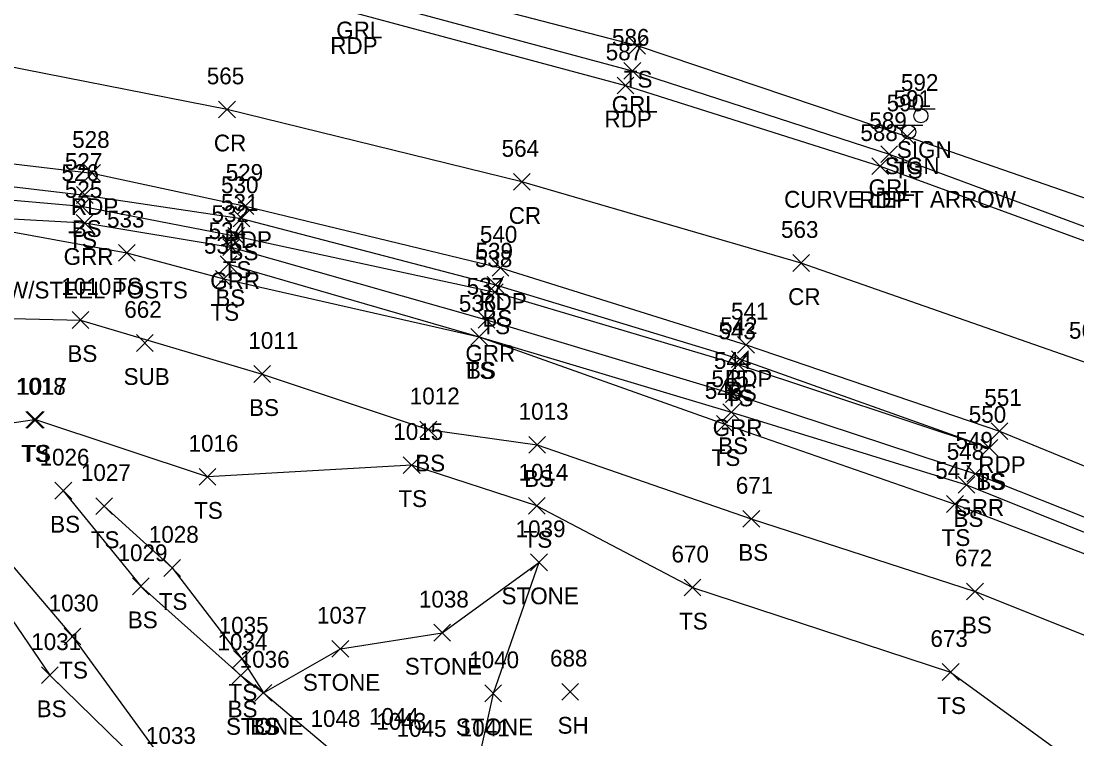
# Model space of a CAD drawing. Extents: x 1485624 to 1495982, y 886445 to 890805.
# Drawn here: x 1495677.5 to 1495803.4, y 890519.9 to 890605.4 of the extents above; entities that cross this region are included whole.
import ezdxf

# ---------------------------------------------------------------- set-up
doc = ezdxf.new("R2010")
doc.units = 0
for name, color, linetype in [('D_I', 7, 'Continuous'), ('L_A', 7, 'Continuous'), ('L_I', 7, 'Continuous'), ('L_TIC', 7, 'Continuous'), ('LASF', 7, 'Continuous'), ('LELB', 7, 'Continuous'), ('P_A', 7, 'Continuous'), ('P_I', 7, 'Continuous'), ('P_TIC', 7, 'Continuous'), ('PET', 7, 'Continuous'), ('PRC', 7, 'Continuous'), ('R_A', 7, 'Continuous'), ('R_C', 7, 'Continuous'), ('R_I', 7, 'Continuous'), ('R_TIC', 7, 'Continuous'), ('RGR', 7, 'Continuous'), ('S_A', 7, 'Continuous'), ('S_C', 7, 'Continuous'), ('S_I', 7, 'Continuous'), ('SSGN', 7, 'Continuous'), ('U_A', 7, 'Continuous'), ('U_I', 7, 'Continuous'), ('U_TIC', 7, 'Continuous')]:
    doc.layers.add(name, color=color, linetype=linetype)

msp = doc.modelspace()

# ---------------------------------------------------------------- linework, layer by layer
at = {"layer": 'L_TIC'}
for points in [[(1495749.98, 890601.51), (1495751.98, 890603.51)], [(1495751.98, 890601.51), (1495749.98, 890603.51)], [(1495782.18, 890590.68), (1495784.18, 890592.68)], [(1495784.18, 890590.68), (1495782.18, 890592.68)], [(1495684.12, 890583.7), (1495686.12, 890585.7)], [(1495686.12, 890583.7), (1495684.12, 890585.7)], [(1495683.75, 890582.37), (1495685.75, 890584.37)], [(1495685.75, 890582.37), (1495683.75, 890584.37)], [(1495702.82, 890580.92), (1495704.82, 890582.92)], [(1495704.82, 890580.92), (1495702.82, 890582.92)], [(1495702.16, 890578.81), (1495704.16, 890580.81)], [(1495704.16, 890578.81), (1495702.16, 890580.81)], [(1495689.14, 890576.82), (1495691.14, 890578.82)], [(1495691.14, 890576.82), (1495689.14, 890578.82)], [(1495701.25, 890575.45), (1495703.25, 890577.45)], [(1495703.25, 890575.45), (1495701.25, 890577.45)], [(1495700.7, 890573.71), (1495702.7, 890575.71)], [(1495702.7, 890573.71), (1495700.7, 890575.71)], [(1495733.08, 890573), (1495735.08, 890575)], [(1495735.08, 890573), (1495733.08, 890575)], [(1495733, 890572.11), (1495735, 890574.11)], [(1495735, 890572.11), (1495733, 890574.11)], [(1495683.61, 890568.8), (1495685.61, 890570.8)], [(1495685.61, 890568.8), (1495683.61, 890570.8)], [(1495731.13, 890566.79), (1495733.13, 890568.79)], [(1495733.13, 890566.79), (1495731.13, 890568.79)], [(1495731.13, 890566.79), (1495733.13, 890568.79)], [(1495733.13, 890566.79), (1495731.13, 890568.79)], [(1495762.03, 890563.51), (1495764.03, 890565.51)], [(1495764.03, 890563.51), (1495762.03, 890565.51)], [(1495762.24, 890564.13), (1495764.24, 890566.13)], [(1495764.24, 890564.13), (1495762.24, 890566.13)], [(1495705.27, 890562.36), (1495707.27, 890564.36)], [(1495707.27, 890562.36), (1495705.27, 890564.36)], [(1495761.2, 890557.81), (1495763.2, 890559.81)], [(1495763.2, 890557.81), (1495761.2, 890559.81)], [(1495678.11, 890556.89), (1495680.11, 890558.89)], [(1495680.11, 890556.89), (1495678.11, 890558.89)], [(1495678.27, 890556.9), (1495680.27, 890558.9)], [(1495680.27, 890556.9), (1495678.27, 890558.9)], [(1495760.45, 890556.4), (1495762.45, 890558.4)], [(1495762.45, 890556.4), (1495760.45, 890558.4)], [(1495725.08, 890555.74), (1495727.08, 890557.74)], [(1495727.08, 890555.74), (1495725.08, 890557.74)], [(1495738.05, 890553.91), (1495740.05, 890555.91)], [(1495740.05, 890553.91), (1495738.05, 890555.91)], [(1495791.96, 890553.55), (1495793.96, 890555.55)], [(1495793.96, 890553.55), (1495791.96, 890555.55)], [(1495791.96, 890553.55), (1495793.96, 890555.55)], [(1495793.96, 890553.55), (1495791.96, 890555.55)], [(1495723.1, 890551.5), (1495725.1, 890553.5)], [(1495725.1, 890551.5), (1495723.1, 890553.5)], [(1495698.75, 890550.1), (1495700.75, 890552.1)], [(1495700.75, 890550.1), (1495698.75, 890552.1)], [(1495681.56, 890548.45), (1495683.56, 890550.45)], [(1495683.56, 890548.45), (1495681.56, 890550.45)], [(1495789.25, 890549.14), (1495791.25, 890551.14)], [(1495791.25, 890549.14), (1495789.25, 890551.14)], [(1495686.43, 890546.61), (1495688.43, 890548.61)], [(1495688.43, 890546.61), (1495686.43, 890548.61)], [(1495738.03, 890546.65), (1495740.03, 890548.65)], [(1495740.03, 890546.65), (1495738.03, 890548.65)], [(1495787.87, 890546.86), (1495789.87, 890548.86)], [(1495789.87, 890546.86), (1495787.87, 890548.86)], [(1495763.59, 890545.09), (1495765.59, 890547.09)], [(1495765.59, 890545.09), (1495763.59, 890547.09)], [(1495738.27, 890539.91), (1495740.27, 890541.91)], [(1495740.27, 890539.91), (1495738.27, 890541.91)], [(1495694.53, 890539.24), (1495696.53, 890541.24)], [(1495696.53, 890539.24), (1495694.53, 890541.24)], [(1495690.81, 890537.05), (1495692.81, 890539.05)], [(1495692.81, 890537.05), (1495690.81, 890539.05)], [(1495756.57, 890536.9), (1495758.57, 890538.9)], [(1495758.57, 890536.9), (1495756.57, 890538.9)], [(1495790.26, 890536.44), (1495792.26, 890538.44)], [(1495792.26, 890536.44), (1495790.26, 890538.44)], [(1495682.67, 890531.06), (1495684.67, 890533.06)], [(1495684.67, 890531.06), (1495682.67, 890533.06)], [(1495726.73, 890531.52), (1495728.73, 890533.52)], [(1495728.73, 890531.52), (1495726.73, 890533.52)], [(1495714.59, 890529.6), (1495716.59, 890531.6)], [(1495716.59, 890529.6), (1495714.59, 890531.6)], [(1495702.86, 890528.41), (1495704.86, 890530.41)], [(1495704.86, 890528.41), (1495702.86, 890530.41)], [(1495679.95, 890526.45), (1495681.95, 890528.45)], [(1495681.95, 890526.45), (1495679.95, 890528.45)], [(1495702.71, 890526.42), (1495704.71, 890528.42)], [(1495704.71, 890526.42), (1495702.71, 890528.42)], [(1495787.35, 890526.83), (1495789.35, 890528.83)], [(1495789.35, 890526.83), (1495787.35, 890528.83)], [(1495742, 890524.48), (1495744, 890526.48)], [(1495744, 890524.48), (1495742, 890526.48)], [(1495705.41, 890524.35), (1495707.41, 890526.35)], [(1495707.41, 890524.35), (1495705.41, 890526.35)], [(1495705.41, 890524.35), (1495707.41, 890526.35)], [(1495707.41, 890524.35), (1495705.41, 890526.35)], [(1495705.41, 890524.35), (1495707.41, 890526.35)], [(1495707.41, 890524.35), (1495705.41, 890526.35)], [(1495705.41, 890524.35), (1495707.41, 890526.35)], [(1495707.41, 890524.35), (1495705.41, 890526.35)], [(1495732.8, 890524.29), (1495734.8, 890526.29)], [(1495734.8, 890524.29), (1495732.8, 890526.29)]]:
    msp.add_lwpolyline(points, dxfattribs=at)
at = {"layer": 'LASF'}
for points in [[(1495706.41, 890525.35), (1495715.59, 890530.6), (1495727.73, 890532.52), (1495739.27, 890540.91), (1495733.8, 890525.29), (1495732.03, 890517.15), (1495730.16, 890501.66), (1495728.74, 890496.24)], [(1495706.41, 890525.35), (1495714.8, 890518.29), (1495709.18, 890508.83), (1495701.89, 890508.36), (1495708.94, 890497.18), (1495716.65, 890495.8), (1495721.33, 890494.3), (1495726.86, 890494.97), (1495728.74, 890496.24)]]:
    msp.add_lwpolyline(points, dxfattribs=at)
at = {"layer": 'LELB'}
for points in [[(1495617.51, 890647.42), (1495659.25, 890631.91), (1495662.58, 890630.34), (1495680.12, 890623), (1495718.11, 890611.07), (1495750.98, 890602.51), (1495783.18, 890591.68), (1495810.94, 890582.07), (1495845.91, 890568.15), (1495889.08, 890548.91)], [(1495661.52, 890587.48), (1495685.12, 890584.7), (1495703.82, 890581.92), (1495734.08, 890574), (1495763.24, 890565.13), (1495792.96, 890554.55)], [(1495640.23, 890572.88), (1495648.59, 890580.73), (1495661.23, 890585.45), (1495684.75, 890583.37), (1495703.16, 890579.81), (1495734, 890573.11), (1495763.03, 890564.51), (1495792.96, 890554.55)], [(1495643.24, 890569.95), (1495650.54, 890577.25), (1495664.27, 890582.53), (1495690.14, 890577.82), (1495701.7, 890574.71), (1495732.13, 890567.79), (1495761.45, 890557.4), (1495788.87, 890547.86), (1495821.91, 890535.22), (1495855.28, 890520.02)], [(1495702.25, 890576.45), (1495732.13, 890567.79), (1495762.2, 890558.81), (1495790.25, 890550.14), (1495822.26, 890537.28), (1495856.79, 890522.39)], [(1495648.08, 890563.04), (1495654.89, 890571.41), (1495663.3, 890570.28), (1495684.61, 890569.8), (1495706.27, 890563.36), (1495726.08, 890556.74), (1495739.05, 890554.91)], [(1495650.44, 890558.06), (1495659.47, 890551.56), (1495670.67, 890542.5), (1495680.95, 890527.45), (1495694.72, 890514.02), (1495701.89, 890508.36)], [(1495739.03, 890547.65), (1495724.1, 890552.5), (1495699.75, 890551.1), (1495679.27, 890557.9), (1495679.11, 890557.89), (1495668.33, 890556.32), (1495662.04, 890554.8), (1495672.43, 890545.26), (1495683.67, 890532.06), (1495695.19, 890516.26), (1495707.45, 890511.95), (1495709.18, 890508.83), (1495715.54, 890502.47), (1495718.87, 890501.79), (1495723.73, 890502.35)], [(1495739.05, 890554.91), (1495764.59, 890546.09)], [(1495682.56, 890549.45), (1495691.81, 890538.05), (1495703.71, 890527.42), (1495706.41, 890525.35)], [(1495687.43, 890547.61), (1495695.53, 890540.24), (1495703.86, 890529.41), (1495706.41, 890525.35)], [(1495739.03, 890547.65), (1495757.57, 890537.9)], [(1495764.59, 890546.09), (1495791.26, 890537.44), (1495825.78, 890523.65), (1495849.15, 890512.9)], [(1495757.57, 890537.9), (1495788.35, 890527.83), (1495828.07, 890498.9), (1495795.98, 890501.66), (1495778.3, 890500.66), (1495774.03, 890506.35), (1495756.49, 890501.63), (1495740.74, 890489.73)]]:
    msp.add_lwpolyline(points, dxfattribs=at)
at = {"layer": 'P_TIC'}
for points in [[(1495748.59, 890596.76), (1495750.59, 890598.76)], [(1495750.59, 890596.76), (1495748.59, 890598.76)], [(1495701.08, 890593.9), (1495703.08, 890595.9)], [(1495703.08, 890593.9), (1495701.08, 890595.9)], [(1495684.99, 890586.32), (1495686.99, 890588.32)], [(1495686.99, 890586.32), (1495684.99, 890588.32)], [(1495778.95, 890587.14), (1495780.95, 890589.14)], [(1495780.95, 890587.14), (1495778.95, 890589.14)], [(1495736.23, 890585.26), (1495738.23, 890587.26)], [(1495738.23, 890585.26), (1495736.23, 890587.26)], [(1495703.29, 890582.39), (1495705.29, 890584.39)], [(1495705.29, 890582.39), (1495703.29, 890584.39)], [(1495733.68, 890575.01), (1495735.68, 890577.01)], [(1495735.68, 890575.01), (1495733.68, 890577.01)], [(1495769.54, 890575.59), (1495771.54, 890577.59)], [(1495771.54, 890575.59), (1495769.54, 890577.59)], [(1495762.96, 890565.85), (1495764.96, 890567.85)], [(1495764.96, 890565.85), (1495762.96, 890567.85)], [(1495793.17, 890555.56), (1495795.17, 890557.56)], [(1495795.17, 890555.56), (1495793.17, 890557.56)]]:
    msp.add_lwpolyline(points, dxfattribs=at)
at = {"layer": 'PET'}
for points in [[(1495609.58, 890624.88), (1495650.02, 890621.06), (1495682.45, 890614.6), (1495716.9, 890606.52), (1495749.59, 890597.76), (1495779.95, 890588.14), (1495810.5, 890576.96), (1495843, 890563.53), (1495882.78, 890545.01)], [(1495611.34, 890596.8), (1495660.14, 890590.36), (1495685.99, 890587.32), (1495704.29, 890583.39), (1495734.68, 890576.01), (1495763.96, 890566.85), (1495794.17, 890556.56), (1495823.36, 890544.58), (1495859.75, 890527.82)]]:
    msp.add_lwpolyline(points, dxfattribs=at)
at = {"layer": 'PRC'}
msp.add_lwpolyline([(1495865.85, 890538.25), (1495835.89, 890551.78), (1495804.87, 890564.57), (1495770.54, 890576.59), (1495737.23, 890586.26), (1495702.08, 890594.9), (1495658.63, 890603.44), (1495614.66, 890611.01)], dxfattribs=at)
at = {"layer": 'R_TIC'}
for points in [[(1495749.4, 890598.5), (1495751.4, 890600.5)], [(1495751.4, 890598.5), (1495749.4, 890600.5)], [(1495780.03, 890588.57), (1495782.03, 890590.57)], [(1495782.03, 890588.57), (1495780.03, 890590.57)], [(1495684.11, 890580.37), (1495686.11, 890582.37)], [(1495686.11, 890580.37), (1495684.11, 890582.37)], [(1495701.59, 890577.48), (1495703.59, 890579.48)], [(1495703.59, 890577.48), (1495701.59, 890579.48)], [(1495732.01, 890568.82), (1495734.01, 890570.82)], [(1495734.01, 890568.82), (1495732.01, 890570.82)], [(1495761.5, 890559.97), (1495763.5, 890561.97)], [(1495763.5, 890559.97), (1495761.5, 890561.97)], [(1495790.3, 890550.45), (1495792.3, 890552.45)], [(1495792.3, 890550.45), (1495790.3, 890552.45)]]:
    msp.add_lwpolyline(points, dxfattribs=at)
at = {"layer": 'RGR'}
for points in [[(1495657.99, 890625.64), (1495670.77, 890620.07), (1495682.61, 890616.63), (1495717.55, 890608.37), (1495750.4, 890599.5), (1495781.03, 890589.57), (1495810.95, 890578.47), (1495843.97, 890564.67), (1495884.04, 890546.25), (1495911.23, 890532.9), (1495928.25, 890525.82), (1495941.85, 890522.12)], [(1495664.27, 890582.53), (1495685.11, 890581.37), (1495702.59, 890578.48), (1495733.01, 890569.82), (1495762.5, 890560.97), (1495791.3, 890551.45), (1495822.57, 890539.06), (1495857.36, 890523.4), (1495878.61, 890513.19), (1495895.11, 890505.02), (1495906, 890498.67), (1495922.02, 890487.12)]]:
    msp.add_lwpolyline(points, dxfattribs=at)
at = {"layer": 'SSGN'}
for p, q in [((1495783.16, 890594.98), (1495786.49, 890594.98)), ((1495784.81, 890594.14), (1495784.81, 890594.14)), ((1495781.72, 890593.04), (1495785.05, 890593.04)), ((1495783.37, 890592.21), (1495783.37, 890592.21))]:
    msp.add_line(p, q, dxfattribs=at)
for centre in [(1495784.81, 890594.14), (1495783.37, 890592.21)]:
    msp.add_circle(centre, 0.833, dxfattribs=at)
at = {"layer": 'U_TIC'}
for points in [[(1495691.28, 890566.06), (1495693.28, 890568.06)], [(1495693.28, 890566.06), (1495691.28, 890568.06)]]:
    msp.add_lwpolyline(points, dxfattribs=at)

# ---------------------------------------------------------------- texts
at = {"layer": 'D_I'}
msp.add_text('1043', height=2, dxfattribs=at).set_placement((1495719.88, 890520.95))
at = {"layer": 'L_A'}
for s, p in [('TS', (1495749.39, 890597.51)), ('TS', (1495781.59, 890586.68)), ('BS', (1495683.56, 890579.7)), ('TS', (1495683.16, 890578.37)), ('BS', (1495702.26, 890576.92)), ('TS', (1495701.57, 890574.81)), ('TS', (1495688.55, 890572.82)), ('BS', (1495700.69, 890571.45)), ('TS', (1495700.11, 890569.71)), ('BS', (1495732.52, 890569)), ('TS', (1495732.41, 890568.11)), ('BS', (1495683.05, 890564.8)), ('TS', (1495730.54, 890562.79)), ('BS', (1495730.57, 890562.79)), ('BS', (1495761.68, 890560.13)), ('BS', (1495704.71, 890558.36)), ('TS', (1495761.44, 890559.51)), ('BS', (1495760.64, 890553.81)), ('TS', (1495677.52, 890552.89)), ('TS', (1495677.68, 890552.9)), ('TS', (1495759.86, 890552.4)), ('BS', (1495724.52, 890551.74)), ('BS', (1495737.49, 890549.91)), ('TS', (1495791.37, 890549.55)), ('BS', (1495791.4, 890549.55)), ('TS', (1495722.51, 890547.5)), ('TS', (1495698.16, 890546.1)), ('BS', (1495788.69, 890545.14)), ('BS', (1495681, 890544.45)), ('TS', (1495685.84, 890542.61)), ('TS', (1495737.44, 890542.65)), ('TS', (1495787.28, 890542.86)), ('BS', (1495763.03, 890541.09)), ('STONE', (1495734.81, 890535.91)), ('TS', (1495693.94, 890535.24)), ('BS', (1495690.25, 890533.05)), ('TS', (1495755.98, 890532.9)), ('BS', (1495789.7, 890532.44)), ('TS', (1495682.08, 890527.06)), ('STONE', (1495723.28, 890527.52)), ('TS', (1495702.27, 890524.41)), ('STONE', (1495711.13, 890525.6)), ('BS', (1495679.39, 890522.45)), ('BS', (1495702.15, 890522.42)), ('TS', (1495786.76, 890522.83)), ('STONE', (1495701.96, 890520.35)), ('STONE', (1495701.96, 890520.35)), ('TS', (1495704.82, 890520.35)), ('BS', (1495704.85, 890520.35)), ('STONE', (1495729.35, 890520.29)), ('SH', (1495741.49, 890520.48))]:
    msp.add_text(s, height=2, dxfattribs=at).set_placement(p)
at = {"layer": 'L_I'}
for s, p in [('590', (1495780.73, 890594.68)), ('527', (1495682.75, 890587.7)), ('526', (1495682.34, 890586.37)), ('530', (1495701.37, 890584.92)), ('531', (1495701.37, 890582.81)), ('533', (1495687.78, 890580.82)), ('534', (1495699.89, 890579.45)), ('535', (1495699.33, 890577.71)), ('538', (1495731.63, 890576.11)), ('539', (1495731.71, 890577)), ('1010', (1495682.32, 890572.8)), ('536', (1495729.72, 890570.79)), ('536', (1495729.72, 890570.79)), ('543', (1495760.67, 890567.51)), ('542', (1495760.87, 890568.13)), ('1011', (1495704.63, 890566.36)), ('1018', (1495676.91, 890560.89)), ('1017', (1495677.06, 890560.9)), ('545', (1495759.83, 890561.81)), ('1012', (1495723.87, 890559.74)), ('546', (1495759.04, 890560.4)), ('1013', (1495736.85, 890557.91)), ('550', (1495790.51, 890557.55)), ('550', (1495790.51, 890557.55)), ('1015', (1495721.9, 890555.5)), ('1016', (1495697.49, 890554.1)), ('1026', (1495679.73, 890552.45)), ('548', (1495787.89, 890553.14)), ('547', (1495786.51, 890550.86)), ('1027', (1495684.66, 890550.61)), ('1014', (1495736.83, 890550.65)), ('671', (1495762.74, 890549.09)), ('1039', (1495736.49, 890543.91)), ('1028', (1495692.76, 890543.24)), ('1029', (1495689.03, 890541.05)), ('670', (1495755.07, 890540.9)), ('672', (1495788.85, 890540.44)), ('1030', (1495680.81, 890535.06)), ('1038', (1495724.96, 890535.52)), ('1037', (1495712.81, 890533.6)), ('1035', (1495701.09, 890532.41)), ('673', (1495785.94, 890530.83)), ('1031', (1495678.74, 890530.45)), ('1034', (1495700.94, 890530.42)), ('1036', (1495703.59, 890528.35)), ('1036', (1495703.59, 890528.35)), ('1036', (1495703.59, 890528.35)), ('1036', (1495703.59, 890528.35)), ('1040', (1495730.95, 890528.29)), ('688', (1495740.59, 890528.48)), ('1048', (1495712.03, 890521.29)), ('1044', (1495719.01, 890521.54)), ('1044', (1495719.01, 890521.54)), ('1045', (1495722.3, 890520.11)), ('1041', (1495729.83, 890520.15)), ('1033', (1495692.42, 890519.26))]:
    msp.add_text(s, height=2, dxfattribs=at).set_placement(p)
at = {"layer": 'P_A'}
for s, p in [('RDP', (1495714.39, 890601.52)), ('RDP', (1495747.08, 890592.76)), ('CR', (1495700.51, 890589.9)), ('RDP', (1495683.47, 890582.32)), ('RDP', (1495777.44, 890583.14)), ('CR', (1495735.67, 890581.26)), ('RDP', (1495701.78, 890578.39)), ('RDP', (1495732.17, 890571.01)), ('CR', (1495768.98, 890571.59)), ('RDP', (1495761.45, 890561.85)), ('RDP', (1495791.65, 890551.56))]:
    msp.add_text(s, height=2, dxfattribs=at).set_placement(p)
at = {"layer": 'P_I'}
for s, p in [('587', (1495747.23, 890600.76)), ('565', (1495699.67, 890597.9)), ('588', (1495777.59, 890591.14)), ('528', (1495683.62, 890590.32)), ('564', (1495734.82, 890589.26)), ('529', (1495701.92, 890586.39)), ('540', (1495732.23, 890579.01)), ('563', (1495768.13, 890579.59)), ('541', (1495762.17, 890569.85)), ('562', (1495802.46, 890567.57)), ('551', (1495792.37, 890559.56))]:
    msp.add_text(s, height=2, dxfattribs=at).set_placement(p)
at = {"layer": 'R_A'}
for s, p in [('GRL', (1495715.1, 890603.37)), ('GRL', (1495747.94, 890594.5)), ('GRL', (1495778.57, 890584.57)), ('GRR', (1495682.6, 890576.37)), ('GRR', (1495700.08, 890573.48)), ('GRR', (1495730.5, 890564.82)), ('GRR', (1495759.98, 890555.97)), ('GRR', (1495788.79, 890546.45))]:
    msp.add_text(s, height=2, dxfattribs=at).set_placement(p)
at = {"layer": 'R_C'}
msp.add_text('SGR W/STEEL POSTS', height=2, dxfattribs=at).set_placement((1495669.32, 890572.37))
at = {"layer": 'R_I'}
for s, p in [('586', (1495747.98, 890602.5)), ('589', (1495778.66, 890592.57)), ('525', (1495682.75, 890584.37)), ('532', (1495700.23, 890581.48)), ('537', (1495730.65, 890572.82)), ('544', (1495760.13, 890563.97)), ('549', (1495788.93, 890554.45))]:
    msp.add_text(s, height=2, dxfattribs=at).set_placement(p)
at = {"layer": 'S_A'}
for p in [(1495781.94, 890589.12), (1495780.5, 890587.19)]:
    msp.add_text('SIGN', height=2, dxfattribs=at).set_placement(p)
at = {"layer": 'S_C'}
msp.add_text('CURVE LEFT ARROW', height=2, dxfattribs=at).set_placement((1495768.5, 890583.19))
at = {"layer": 'S_I'}
for s, p in [('592', (1495782.43, 890597.12)), ('591', (1495781.55, 890595.19))]:
    msp.add_text(s, height=2, dxfattribs=at).set_placement(p)
at = {"layer": 'U_A'}
msp.add_text('SUB', height=2, dxfattribs=at).set_placement((1495689.75, 890562.06))
at = {"layer": 'U_I'}
msp.add_text('662', height=2, dxfattribs=at).set_placement((1495689.83, 890570.06))

doc.saveas('drawing.dxf')
